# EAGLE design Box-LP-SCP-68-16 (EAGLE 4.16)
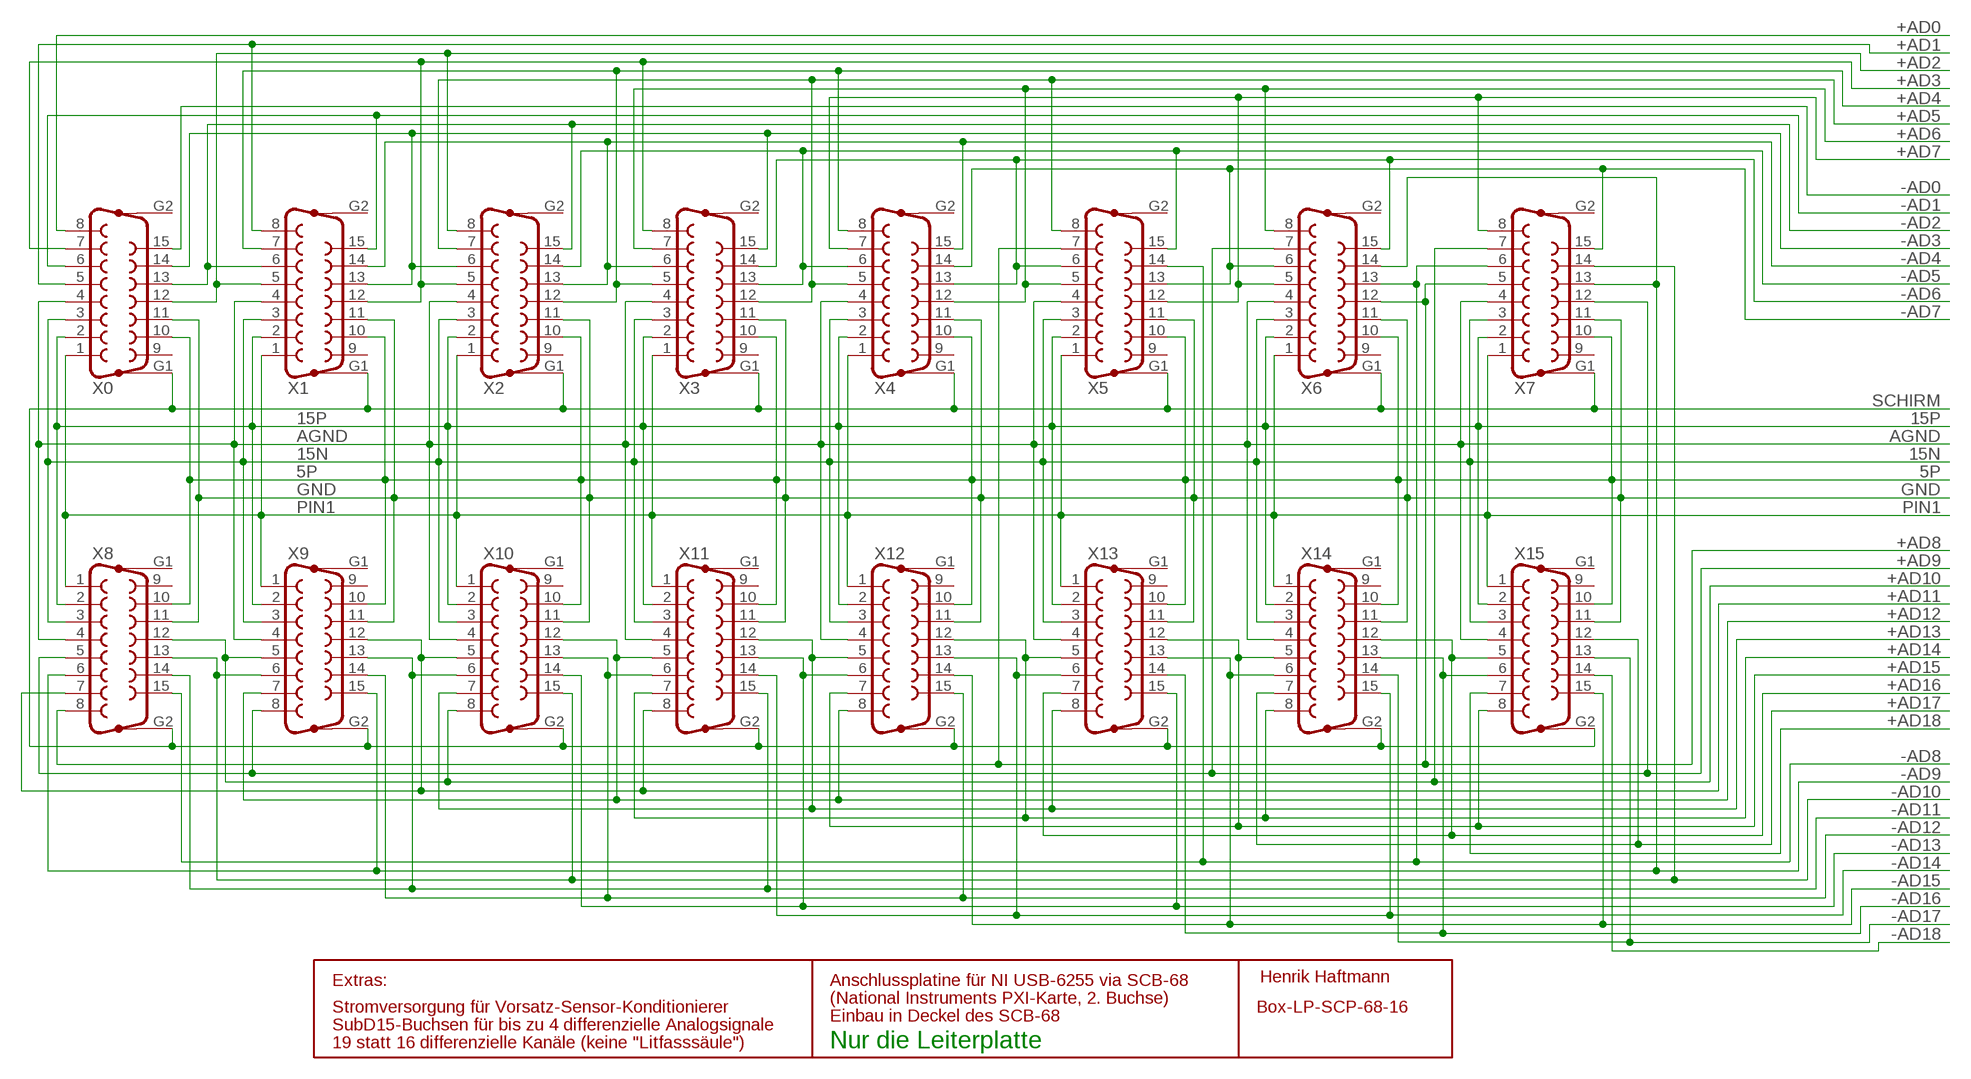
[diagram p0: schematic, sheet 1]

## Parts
X0  F15VP  [F15VP]
X1  F15VP  [F15VP]
X2  F15VP  [F15VP]
X3  F15VP  [F15VP]
X4  F15VP  [F15VP]
X5  F15VP  [F15VP]
X6  F15VP  [F15VP]
X7  F15VP  [F15VP]
X8  F15VP  [F15VP]
X9  F15VP  [F15VP]
X10  F15VP  [F15VP]
X11  F15VP  [F15VP]
X12  F15VP  [F15VP]
X13  F15VP  [F15VP]
X14  F15VP  [F15VP]
X15  F15VP  [F15VP]

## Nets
5P: X0.10 X1.10 X2.10 X3.10 X4.10 X5.10 X6.10 X7.10 X8.10 X9.10 X10.10 X11.10 X12.10 X13.10 X14.10 X15.10
15N: X0.3 X1.3 X2.3 X3.3 X4.3 X5.3 X6.3 X7.3 X8.3 X9.3 X10.3 X11.3 X12.3 X13.3 X14.3 X15.3
15P: X0.2 X1.2 X2.2 X3.2 X4.2 X5.2 X6.2 X7.2 X8.2 X9.2 X10.2 X11.2 X12.2 X13.2 X14.2 X15.2
+AD0: X0.8
+AD1: X0.5 X1.8
+AD2: X0.12 X1.5 X2.8
+AD3: X0.7 X1.12 X2.5 X3.8
+AD4: X1.7 X2.12 X3.5 X4.8
+AD5: X2.7 X3.12 X4.5 X5.8
+AD6: X3.7 X4.12 X5.5 X6.8
+AD7: X4.7 X5.12 X6.5 X7.8
+AD8: X5.7 X6.12 X7.5 X8.8
+AD9: X6.7 X7.12 X8.5 X9.8
+AD10: X7.7 X8.12 X9.5 X10.8
+AD11: X8.7 X9.12 X10.5 X11.8
+AD12: X9.7 X10.12 X11.5 X12.8
+AD13: X10.7 X11.12 X12.5 X13.8
+AD14: X11.7 X12.12 X13.5 X14.8
+AD15: X12.7 X13.12 X14.5 X15.8
+AD16: X13.7 X14.12 X15.5
+AD17: X14.7 X15.12
+AD18: X15.7
-AD0: X0.15
-AD1: X0.6 X1.15
-AD2: X0.13 X1.6 X2.15
-AD3: X0.14 X1.13 X2.6 X3.15
-AD4: X1.14 X2.13 X3.6 X4.15
-AD5: X2.14 X3.13 X4.6 X5.15
-AD6: X3.14 X4.13 X5.6 X6.15
-AD7: X4.14 X5.13 X6.6 X7.15
-AD8: X5.14 X6.13 X7.6 X8.15
-AD9: X6.14 X7.13 X8.6 X9.15
-AD10: X7.14 X8.13 X9.6 X10.15
-AD11: X8.14 X9.13 X10.6 X11.15
-AD12: X9.14 X10.13 X11.6 X12.15
-AD13: X10.14 X11.13 X12.6 X13.15
-AD14: X11.14 X12.13 X13.6 X14.15
-AD15: X12.14 X13.13 X14.6 X15.15
-AD16: X13.14 X14.13 X15.6
-AD17: X14.14 X15.13
-AD18: X15.14
AGND: X0.4 X1.4 X2.4 X3.4 X4.4 X5.4 X6.4 X7.4 X8.4 X9.4 X10.4 X11.4 X12.4 X13.4 X14.4 X15.4
GND: X0.11 X1.11 X2.11 X3.11 X4.11 X5.11 X6.11 X7.11 X8.11 X9.11 X10.11 X11.11 X12.11 X13.11 X14.11 X15.11
PIN1: X0.1 X1.1 X2.1 X3.1 X4.1 X5.1 X6.1 X7.1 X8.1 X9.1 X10.1 X11.1 X12.1 X13.1 X14.1 X15.1
SCHIRM: X0.G1 X1.G1 X2.G1 X3.G1 X4.G1 X5.G1 X6.G1 X7.G1 X8.G2 X9.G2 X10.G2 X11.G2 X12.G2 X13.G2 X14.G2 X15.G2
Unconnected: X0.9 X0.G2 X1.9 X1.G2 X2.9 X2.G2 X3.9 X3.G2 X4.9 X4.G2 X5.9 X5.G2 X6.9 X6.G2 X7.9 X7.G2 X8.9 X8.G1 X9.9 X9.G1 X10.9 X10.G1 X11.9 X11.G1 X12.9 X12.G1 X13.9 X13.G1 X14.9 X14.G1 X15.9 X15.G1

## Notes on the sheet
- Extras: | Anschlussplatine für NI USB-6255 via SCB-68 | Henrik Haftmann
- (National Instruments PXI-Karte, 2. Buchse)
- Stromversorgung für Vorsatz-Sensor-Konditionierer
- Einbau in Deckel des SCB-68
- SubD15-Buchsen für bis zu 4 differenzielle Analogsignale
- 19 statt 16 differenzielle Kanäle (keine "Litfasssäule") | Nur die Leiterplatte

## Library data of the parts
X0 X1-X15 = con-subd:F15VP: SUB-D

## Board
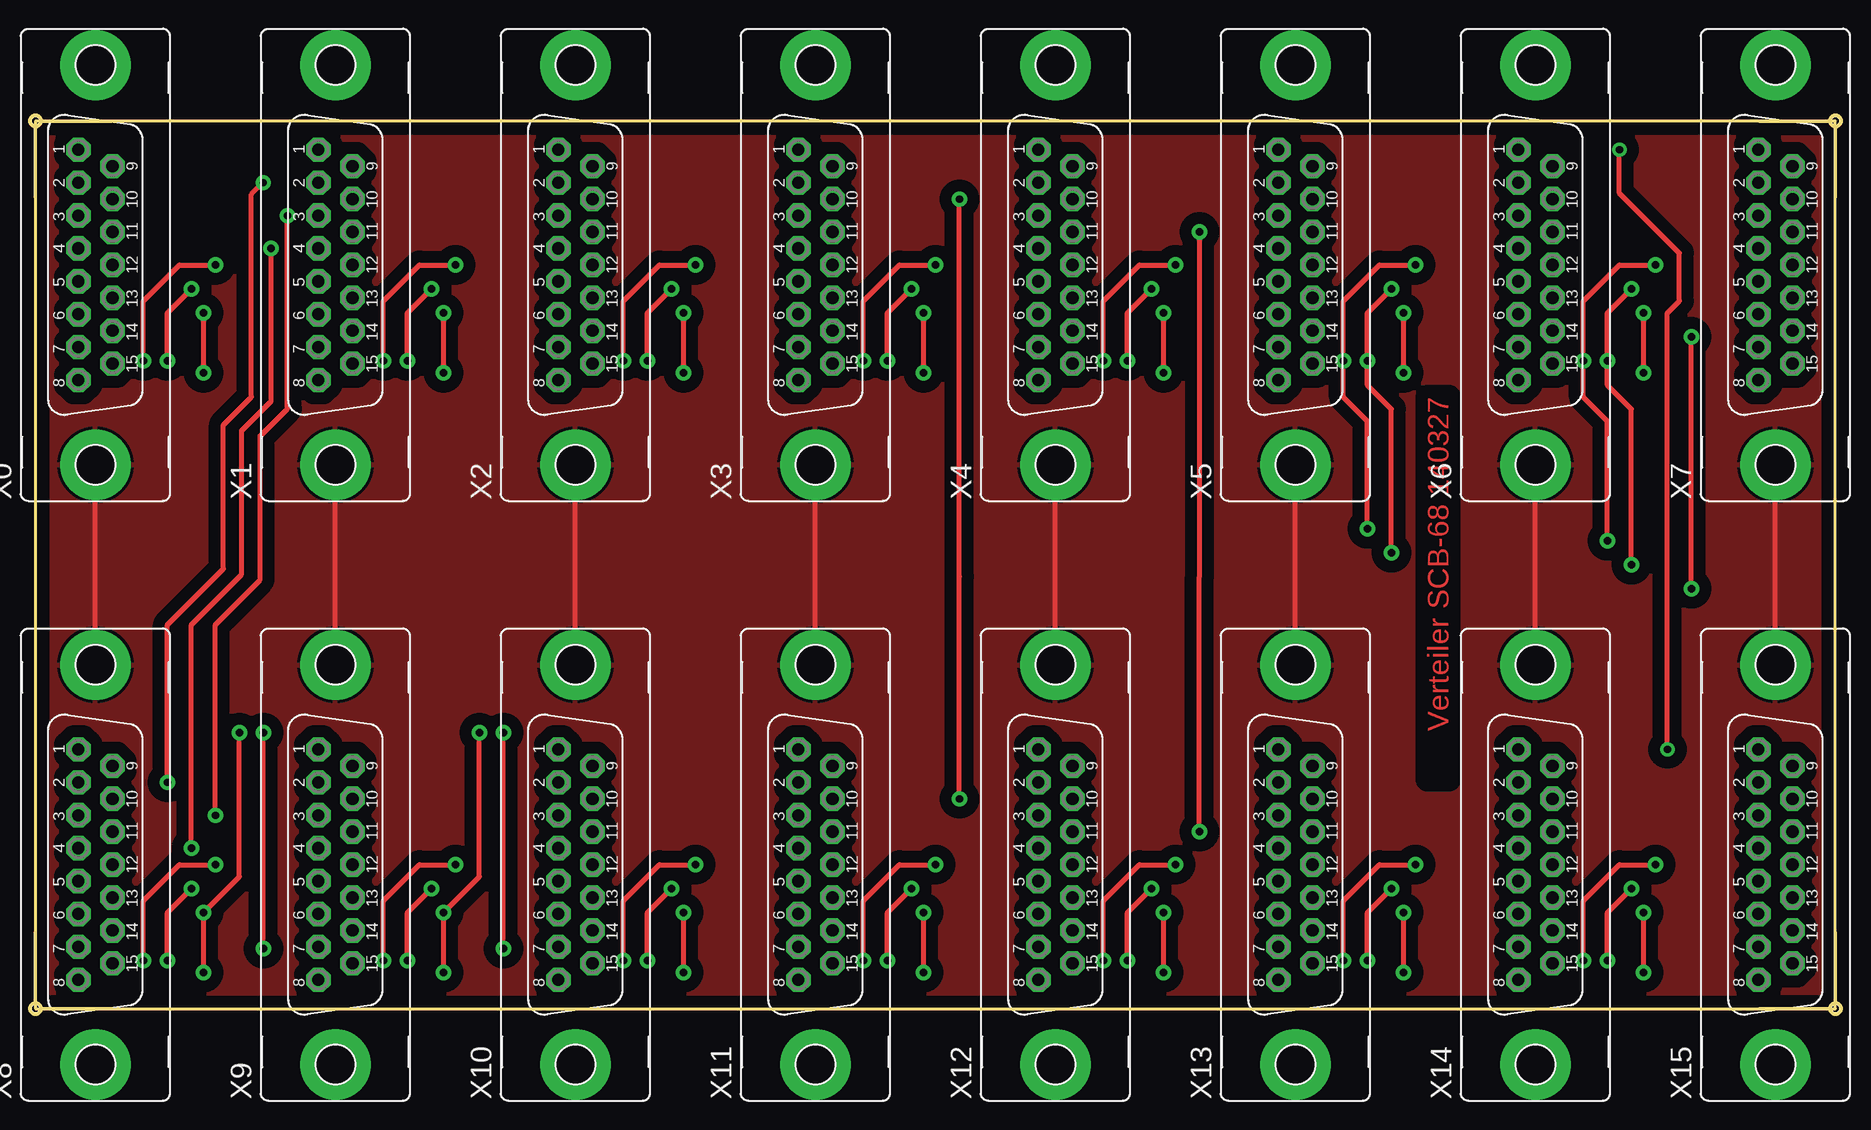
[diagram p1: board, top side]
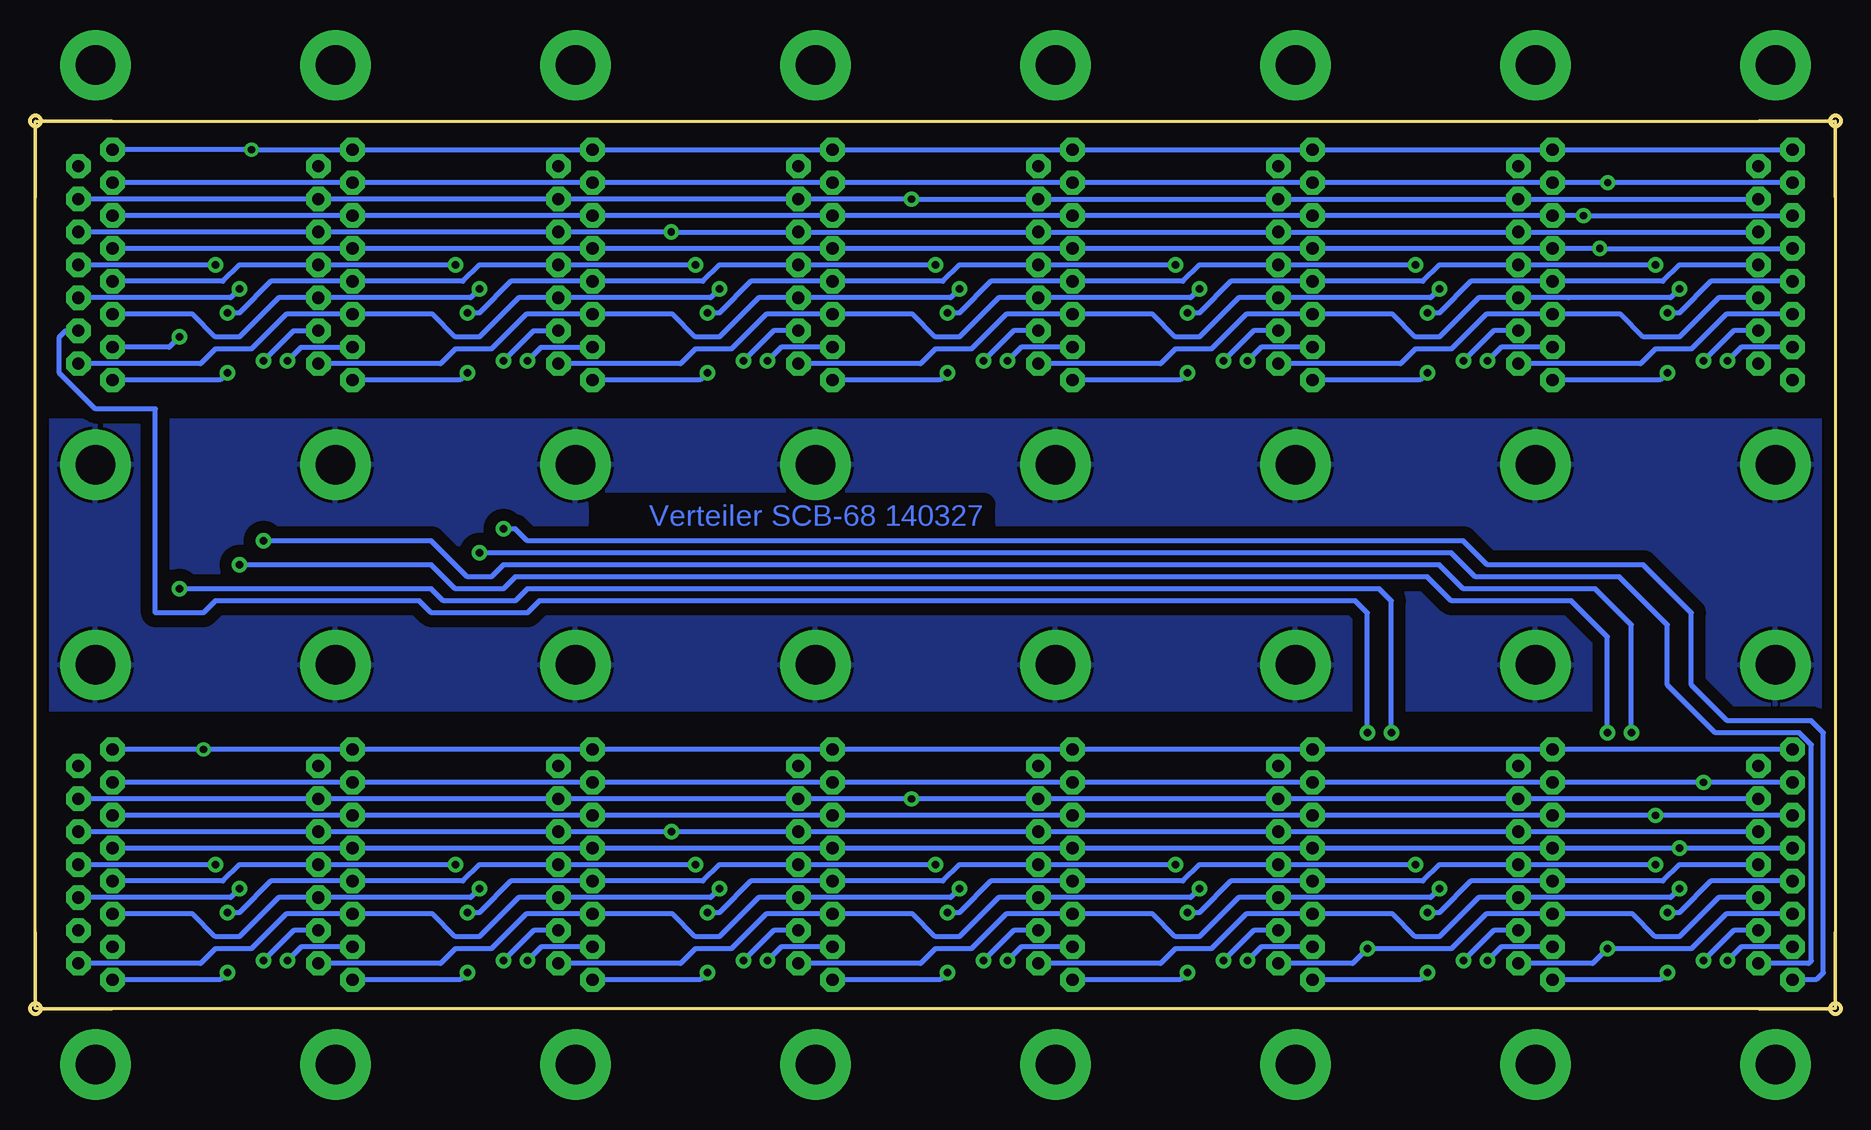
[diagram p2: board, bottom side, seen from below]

Size 150.91 x 74.91 mm. Coordinates in mm from the lower left corner, seen from the top.
Outline: 0.45,0.45 150.45,0.45 150.45,74.45 0.45,74.45 0.45,0.45
Copper layers (1*16): Top 0.035mm / dielectric 1.5mm / Bottom 0.035mm
Design rules "Felber": minimum track width 0.15mm, minimum drill 0.3mm, track to track 0.15mm, track to pad 0.15mm, pad to pad 0.15mm, via to via 0.15mm, smd to smd 0mil, copper to edge 0.3mm, drill to drill 0.3mm, minimum pad ring 10mil, minimum via ring 8mil, stop-mask expansion 4mil, vias tented up to drill 0mil, thermal gap 10mil

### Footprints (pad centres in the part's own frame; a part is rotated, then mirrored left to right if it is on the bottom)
AUSRICHTER = hole 0.6: 0,0
F15VP = drill 1.016 octagon: 1 9.601,1.422; 2 6.858,1.422; 3 4.115,1.422; 4 1.372,1.422; 5 -1.372,1.422; 6 -4.115,1.422; 7 -6.858,1.422; 8 -9.601,1.422; 9 8.23,-1.422; 10 5.486,-1.422; 11 2.743,-1.422; 12 0,-1.422; 13 -2.743,-1.422; 14 -5.486,-1.422; 15 -8.23,-1.422 | drill 3.302 pad 5.08 round: G1 -16.662,0; G2 16.662,0

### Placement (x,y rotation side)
U$1  [AUSRICHTER]  0.45,0.45 0 top
U$2  [AUSRICHTER]  150.45,0.45 90 top
U$3  [AUSRICHTER]  150.45,74.45 180 top
U$4  [AUSRICHTER]  0.45,74.45 270 top
X0  5.45,62.45 90 top
X1  25.45,62.45 90 top
X2  45.45,62.45 90 top
X3  65.45,62.45 90 top
X4  85.45,62.45 90 top
X5  105.45,62.45 90 top
X6  125.45,62.45 90 top
X7  145.45,62.45 90 top
X8  5.45,12.45 90 top
X9  25.45,12.45 90 top
X10  45.45,12.45 90 top
X11  65.45,12.45 90 top
X12  85.45,12.45 90 top
X13  105.45,12.45 90 top
X14  125.45,12.45 90 top
X15  145.45,12.45 90 top

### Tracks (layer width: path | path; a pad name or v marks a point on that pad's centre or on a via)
5P  (via drill 0.6 pad 1.27)
  Top 0.406: 77.45,36.45 v77.45,67.94 | 77.45,36.45 | v77.45,17.94 77.45,36.45
  Bottom 0.406: X0.10 X1.10 X2.10 X3.10 v77.45,67.94 X4.10 X5.10 X6.10 X7.10 | X8.10 X9.10 35.45,17.94 X10.10 X11.10 v77.45,17.94 X12.10 X13.10 X14.10 X15.10
15N  (via drill 0.6 pad 1.27)
  Top 0.406: v21.45,66.57 21.45,50.45 19.18,48.18 19.18,36.18 15.45,32.45 v15.45,16.57
  Bottom 0.406: X0.3 v21.45,66.57 X1.3 X2.3 X3.3 X4.3 X5.3 X6.3 X7.3 | X8.3 v15.45,16.57 X9.3 X10.3 X11.3 X12.3 X13.3 X14.3 X15.3
15P  (via drill 0.6 pad 1.27)
  Top 0.406: v11.45,19.31 11.45,32.45 16.1,37.1 16.1,49.1 18.45,51.45 18.45,68.33 v19.43,69.31
  Bottom 0.406: X0.2 v19.43,69.31 X1.2 X2.2 X3.2 X4.2 X5.2 X6.2 X7.2 | X8.2 v11.45,19.31 X9.2 X10.2 X11.2 X12.2 X13.2 X14.2 X15.2
+AD1  (via drill 0.6 pad 1.27)
  Top 0.406: v14.45,58.45 v14.45,53.45
  Bottom 0.406: X0.5 10.83,61.08 13.45,58.45 v14.45,58.45 | X1.8 15.06,52.85 v14.45,53.45
+AD2  (via drill 0.6 pad 1.27)
  Top 0.406: v34.45,58.45 v34.45,53.45
  Bottom 0.406: X0.12 13.45,62.45 14.83,61.08 X1.5 30.83,61.08 33.45,58.45 v34.45,58.45 | X2.8 35.06,52.85 v34.45,53.45
+AD3  (via drill 0.6 pad 1.27)
  Top 0.406: v54.45,58.45 v54.45,53.45 | v9.45,54.45 9.45,59.45 12.45,62.45 v15.45,62.45
  Bottom 0.406: v54.45,58.45 53.45,58.45 50.83,61.08 X2.5 34.83,61.08 33.45,62.45 X1.12 v15.45,62.45 | X3.8 55.06,52.85 v54.45,53.45 | X0.7 8.31,55.6 v9.45,54.45
+AD4  (via drill 0.6 pad 1.27)
  Top 0.406: v74.45,58.45 v74.45,53.45 | v29.45,54.45 29.45,59.45 32.45,62.45 v35.45,62.45
  Bottom 0.406: v74.45,58.45 73.45,58.45 70.83,61.08 X3.5 54.83,61.08 53.45,62.45 X2.12 v35.45,62.45 | X4.8 75.06,52.85 v74.45,53.45 | X1.7 28.31,55.6 v29.45,54.45
+AD5  (via drill 0.6 pad 1.27)
  Top 0.406: v94.45,58.45 v94.45,53.45 | v55.45,62.45 52.45,62.45 49.45,59.45 v49.45,54.45
  Bottom 0.406: v94.45,58.45 93.45,58.45 90.83,61.08 X4.5 74.83,61.08 73.45,62.45 X3.12 v55.45,62.45 | X5.8 95.06,52.85 v94.45,53.45 | X2.7 48.31,55.6 v49.45,54.45
+AD6  (via drill 0.6 pad 1.27)
  Top 0.406: v114.45,58.45 v114.45,53.45 | v69.45,54.45 69.45,59.45 72.45,62.45 v75.45,62.45
  Bottom 0.406: v114.45,58.45 113.45,58.45 110.83,61.08 X5.5 94.83,61.08 93.45,62.45 X4.12 v75.45,62.45 | X6.8 115.06,52.85 v114.45,53.45 | X3.7 68.31,55.6 v69.45,54.45
+AD7  (via drill 0.6 pad 1.27)
  Top 0.406: v134.45,58.45 v134.45,53.45 | v89.45,54.45 89.45,59.45 92.45,62.45 v95.45,62.45
  Bottom 0.406: v134.45,58.45 133.45,58.45 130.83,61.08 X6.5 114.83,61.08 113.45,62.45 X5.12 v95.45,62.45 | X7.8 135.06,52.85 v134.45,53.45 | X4.7 88.31,55.6 v89.45,54.45
+AD8  (via drill 0.6 pad 1.27)
  Top 0.406: v115.45,62.45 112.45,62.45 109.45,59.45 v109.45,54.45 109.45,51.45 111.45,49.45 v111.45,40.45
  Bottom 0.406: X7.5 134.83,61.08 133.45,62.45 X6.12 v115.45,62.45 | X8.8 2.06,2.85 1.45,3.45 1.45,23.45 2.45,24.45 9.45,24.45 12.45,27.45 12.45,33.45 16.45,37.45 29.45,37.45 31.45,39.45 109.45,39.45 110.45,40.45 v111.45,40.45 | X5.7 108.31,55.6 v109.45,54.45
+AD9  (via drill 0.6 pad 1.27)
  Top 0.406: v14.45,3.45 v14.45,8.45 17.45,11.45 v17.45,23.45 | v131.45,39.45 131.45,49.45 129.45,51.45 v129.45,54.45 129.45,59.45 132.45,62.45 v135.45,62.45
  Bottom 0.406: X8.5 10.83,11.08 13.45,8.45 v14.45,8.45 | X9.8 15.06,2.85 v14.45,3.45 | v17.45,23.45 17.45,32.45 20.45,35.45 31.45,35.45 33.45,37.45 111.45,37.45 112.45,36.45 114.45,36.45 117.45,39.45 v131.45,39.45 | X6.7 128.31,55.6 v129.45,54.45 | v135.45,62.45 X7.12
+AD10  (via drill 0.6 pad 1.27)
  Top 0.406: v34.45,3.45 v34.45,8.45 37.45,11.45 v37.45,23.45 | v138.45,35.45 v138.45,56.45
  Bottom 0.406: v34.45,8.45 33.45,8.45 30.83,11.08 X9.5 14.83,11.08 13.45,12.45 X8.12 | X10.8 35.06,2.85 v34.45,3.45 | X7.7 139.31,55.6 v138.45,56.45 | v138.45,35.45 117.45,35.45 116.45,34.45 110.45,34.45 109.45,35.45 38.45,35.45 37.45,34.45 v37.45,23.45
+AD11  (via drill 0.6 pad 1.27)
  Top 0.406: v54.45,8.45 v54.45,3.45 | v9.45,4.45 9.45,9.45 12.45,12.45 v15.45,12.45
  Bottom 0.406: v54.45,8.45 53.45,8.45 50.83,11.08 X10.5 34.83,11.08 33.45,12.45 X9.12 v15.45,12.45 | X11.8 55.06,2.85 v54.45,3.45 | X8.7 8.31,5.6 v9.45,4.45
+AD12  (via drill 0.6 pad 1.27)
  Top 0.406: v74.45,8.45 v74.45,3.45 | v29.45,4.45 29.45,9.45 32.45,12.45 v35.45,12.45
  Bottom 0.406: v74.45,8.45 73.45,8.45 70.83,11.08 X11.5 54.83,11.08 53.45,12.45 X10.12 v35.45,12.45 | X12.8 75.06,2.85 v74.45,3.45 | X9.7 28.31,5.6 v29.45,4.45
+AD13  (via drill 0.6 pad 1.27)
  Top 0.406: v94.45,8.45 v94.45,3.45 | v49.45,4.45 49.45,9.45 52.45,12.45 v55.45,12.45
  Bottom 0.406: v94.45,8.45 93.45,8.45 90.83,11.08 X12.5 74.83,11.08 73.45,12.45 X11.12 v55.45,12.45 | X13.8 95.06,2.85 v94.45,3.45 | X10.7 48.31,5.6 v49.45,4.45
+AD14  (via drill 0.6 pad 1.27)
  Top 0.406: v114.45,8.45 v114.45,3.45 | v69.45,4.45 69.45,9.45 72.45,12.45 v75.45,12.45
  Bottom 0.406: v114.45,8.45 113.45,8.45 110.83,11.08 X13.5 94.83,11.08 93.45,12.45 X12.12 v75.45,12.45 | X14.8 115.06,2.85 v114.45,3.45 | X11.7 68.31,5.6 v69.45,4.45
+AD15  (via drill 0.6 pad 1.27)
  Top 0.406: v134.45,8.45 v134.45,3.45 | v89.45,4.45 89.45,9.45 92.45,12.45 v95.45,12.45
  Bottom 0.406: v134.45,8.45 133.45,8.45 130.83,11.08 X14.5 114.83,11.08 113.45,12.45 X13.12 v95.45,12.45 | X15.8 135.06,2.85 v134.45,3.45 | X12.7 88.31,5.6 v89.45,4.45
+AD16  (via drill 0.6 pad 1.27)
  Top 0.406: v109.45,4.45 109.45,9.45 112.45,12.45 v115.45,12.45
  Bottom 0.406: X13.7 108.31,5.6 v109.45,4.45 | v115.45,12.45 X14.12 133.45,12.45 134.83,11.08 X15.5
+AD17  (via drill 0.6 pad 1.27)
  Top 0.406: v129.45,4.45 129.45,9.45 132.45,12.45 v135.45,12.45
  Bottom 0.406: X14.7 128.31,5.6 v129.45,4.45 | v135.45,12.45 X15.12
-AD1
  Bottom 0.406: X0.6 9.57,58.34 12.45,55.45 15.45,55.45 16.68,54.22 X1.15
-AD2
  Bottom 0.406: X0.13 10.2,59.71 13.45,56.45 16.45,56.45 18.34,58.34 X1.6 29.57,58.34 32.45,55.45 35.45,55.45 36.68,54.22 X2.15
-AD3  (via drill 0.6 pad 1.27)
  Top 0.406: v11.45,54.45 11.45,58.45 v13.45,60.45
  Bottom 0.406: X3.15 56.68,54.22 55.45,55.45 52.45,55.45 49.57,58.34 X2.6 37.34,58.34 35.45,56.45 33.45,56.45 30.2,59.71 X1.13 22.71,59.71 14.2,59.71 v13.45,60.45 | X0.14 8.94,56.97 v11.45,54.45
-AD4  (via drill 0.6 pad 1.27)
  Top 0.406: v31.45,54.45 31.45,58.45 v33.45,60.45
  Bottom 0.406: X4.15 76.68,54.22 75.45,55.45 72.45,55.45 69.57,58.34 X3.6 57.34,58.34 55.45,56.45 53.45,56.45 50.2,59.71 X2.13 34.2,59.71 v33.45,60.45 | X1.14 28.94,56.97 v31.45,54.45
-AD5  (via drill 0.6 pad 1.27)
  Top 0.406: v51.45,54.45 51.45,58.45 v53.45,60.45
  Bottom 0.406: X5.15 96.68,54.22 95.45,55.45 92.45,55.45 89.57,58.34 X4.6 77.34,58.34 75.45,56.45 73.45,56.45 70.2,59.71 X3.13 54.2,59.71 v53.45,60.45 | X2.14 48.94,56.97 v51.45,54.45
-AD6  (via drill 0.6 pad 1.27)
  Top 0.406: v71.45,54.45 71.45,58.45 v73.45,60.45
  Bottom 0.406: X6.15 116.68,54.22 115.45,55.45 112.45,55.45 109.57,58.34 X5.6 97.34,58.34 95.45,56.45 93.45,56.45 90.2,59.71 X4.13 74.2,59.71 v73.45,60.45 | X3.14 68.94,56.97 v71.45,54.45
-AD7  (via drill 0.6 pad 1.27)
  Top 0.406: v91.45,54.45 91.45,58.45 v93.45,60.45
  Bottom 0.406: X7.15 136.68,54.22 135.45,55.45 132.45,55.45 129.57,58.34 X6.6 117.34,58.34 115.45,56.45 113.45,56.45 110.2,59.71 X5.13 94.2,59.71 v93.45,60.45 | X4.14 88.94,56.97 v91.45,54.45
-AD8  (via drill 0.6 pad 1.27)
  Top 0.406: v113.45,60.45 111.45,58.45 v111.45,54.45 111.45,52.45 113.45,50.45 v113.45,38.45
  Bottom 0.406: X7.6 137.34,58.34 135.45,56.45 133.45,56.45 130.2,59.71 X6.13 114.2,59.71 v113.45,60.45 | X8.15 2.68,4.22 2.45,4.45 2.45,22.45 3.45,23.45 10.45,23.45 14.45,27.45 14.45,32.45 18.45,36.45 30.45,36.45 32.45,38.45 v113.45,38.45 | X5.14 108.94,56.97 v111.45,54.45
-AD9  (via drill 0.6 pad 1.27)
  Top 0.406: v133.45,37.45 133.45,50.45 131.45,52.45 v131.45,54.45 131.45,58.45 v133.45,60.45 | v19.45,5.45 v19.45,23.45
  Bottom 0.406: X8.6 9.57,8.34 12.45,5.45 v19.45,5.45 20.68,4.22 X9.15 | v19.45,23.45 19.45,31.45 22.45,34.45 32.45,34.45 34.45,36.45 110.45,36.45 111.45,35.45 115.45,35.45 117.45,37.45 v133.45,37.45 | X6.14 128.94,56.97 v131.45,54.45 | X7.13 134.2,59.71 v133.45,60.45
-AD10  (via drill 0.6 pad 1.27)
  Top 0.406: v39.45,5.45 v39.45,23.45
  Bottom 0.406: X8.13 10.2,9.71 13.45,6.45 15.45,6.45 17.34,8.34 X9.6 29.57,8.34 32.45,5.45 v39.45,5.45 40.68,4.22 X10.15 | X7.14 147.94,56.97 148.45,56.45 148.45,53.45 145.45,50.45 140.45,50.45 140.45,33.45 136.45,33.45 135.45,34.45 118.45,34.45 117.45,33.45 109.45,33.45 108.45,34.45 40.45,34.45 39.45,33.45 v39.45,23.45
-AD11  (via drill 0.6 pad 1.27)
  Top 0.406: v11.45,4.45 11.45,8.45 v13.45,10.45
  Bottom 0.406: X11.15 56.68,4.22 55.45,5.45 52.45,5.45 49.57,8.34 X10.6 37.34,8.34 35.45,6.45 33.45,6.45 30.2,9.71 X9.13 14.2,9.71 v13.45,10.45 | X8.14 8.94,6.97 v11.45,4.45
-AD12  (via drill 0.6 pad 1.27)
  Top 0.406: v31.45,4.45 31.45,8.45 v33.45,10.45
  Bottom 0.406: X12.15 76.68,4.22 75.45,5.45 72.45,5.45 69.57,8.34 X11.6 57.34,8.34 55.45,6.45 53.45,6.45 50.2,9.71 X10.13 34.2,9.71 v33.45,10.45 | X9.14 28.94,6.97 v31.45,4.45
-AD13  (via drill 0.6 pad 1.27)
  Top 0.406: v51.45,4.45 51.45,8.45 v53.45,10.45
  Bottom 0.406: X13.15 96.68,4.22 95.45,5.45 92.45,5.45 89.57,8.34 X12.6 77.34,8.34 75.45,6.45 73.45,6.45 70.2,9.71 X11.13 54.2,9.71 v53.45,10.45 | X10.14 48.94,6.97 v51.45,4.45
-AD14  (via drill 0.6 pad 1.27)
  Top 0.406: v71.45,4.45 71.45,8.45 v73.45,10.45
  Bottom 0.406: X14.15 116.68,4.22 115.45,5.45 112.45,5.45 109.57,8.34 X13.6 97.34,8.34 95.45,6.45 93.45,6.45 90.2,9.71 X12.13 74.2,9.71 v73.45,10.45 | X11.14 68.94,6.97 v71.45,4.45
-AD15  (via drill 0.6 pad 1.27)
  Top 0.406: v91.45,4.45 91.45,8.45 v93.45,10.45
  Bottom 0.406: X15.15 136.68,4.22 135.45,5.45 132.45,5.45 129.57,8.34 X14.6 117.34,8.34 115.45,6.45 113.45,6.45 110.2,9.71 X13.13 94.2,9.71 v93.45,10.45 | X12.14 88.94,6.97 v91.45,4.45
-AD16  (via drill 0.6 pad 1.27)
  Top 0.406: v111.45,4.45 111.45,8.45 v113.45,10.45
  Bottom 0.406: X13.14 108.94,6.97 v111.45,4.45 | v113.45,10.45 114.2,9.71 X14.13 130.2,9.71 133.45,6.45 135.45,6.45 137.34,8.34 X15.6
-AD17  (via drill 0.6 pad 1.27)
  Top 0.406: v131.45,4.45 131.45,8.45 v133.45,10.45
  Bottom 0.406: X14.14 128.94,6.97 v131.45,4.45 | X15.13 134.2,9.71 v133.45,10.45
AGND  (via drill 0.6 pad 1.27)
  Top 0.406: v20.09,63.83 20.09,51.09 17.64,48.64 17.64,36.64 13.45,32.45 v13.45,13.83
  Bottom 0.406: X0.4 v20.09,63.83 X1.4 X2.4 X3.4 X4.4 X5.4 X6.4 X7.4 | X8.4 v13.45,13.83 X9.4 X10.4 X11.4 X12.4 X13.4 X14.4 X15.4
GND  (via drill 0.6 pad 1.27)
  Top 0.406: v97.46,65.2 97.46,36.46 97.45,36.45 v97.45,15.2
  Bottom 0.406: X0.11 X1.11 X2.11 X3.11 X4.11 v97.46,65.2 X5.11 X6.11 X7.11 | X8.11 X9.11 33.45,15.2 X10.11 X11.11 X12.11 v97.45,15.2 X13.11 X14.11 X15.11
PIN1  (via drill 0.6)
  Top 0.406: v132.45,72.06 132.45,68.45 137.45,63.45 137.45,59.45 136.45,58.45 v136.45,22.06
  Bottom 0.406: X8.1 X9.1 X10.1 X11.1 X12.1 X13.1 X14.1 v136.45,22.06 X15.1 | X0.1 X1.1 X2.1 X3.1 X4.1 X5.1 X6.1 v132.45,72.06 X7.1
SCHIRM
  Top 0.406: X10.G2 X2.G1 | X9.G2 X1.G1 | X8.G2 X0.G1 | X11.G2 X3.G1 | X12.G2 X4.G1 | X13.G2 X5.G1 | X14.G2 X6.G1 | X15.G2 X7.G1
  pour Top (isolate 1): 1.45,73.45 149.45,73.45 149.45,1.45 1.45,1.45
  pour Bottom (isolate 1): 1.45,49.45 149.45,49.45 149.45,25.45 1.45,25.45

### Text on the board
Top: Verteiler SCB-68 140327
Bottom: Verteiler SCB-68 140327
Measures: 82 | 150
